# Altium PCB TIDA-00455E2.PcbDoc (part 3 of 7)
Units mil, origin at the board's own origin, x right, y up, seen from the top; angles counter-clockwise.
Board outline 6693 x 6693.1 mil, 8 copper layers (Layer 1 - Top Layer, Layer 2 - GND, Layer 3 - Sensitive, Layer 4 - GND, Layer 5 - PWR, Layer 6 - Signal, Layer 7 - GND, Layer 8 - Bottom Layer), stack 63.122 mil thick; 537 components, 407 nets, 1686 pads, 1249 vias.
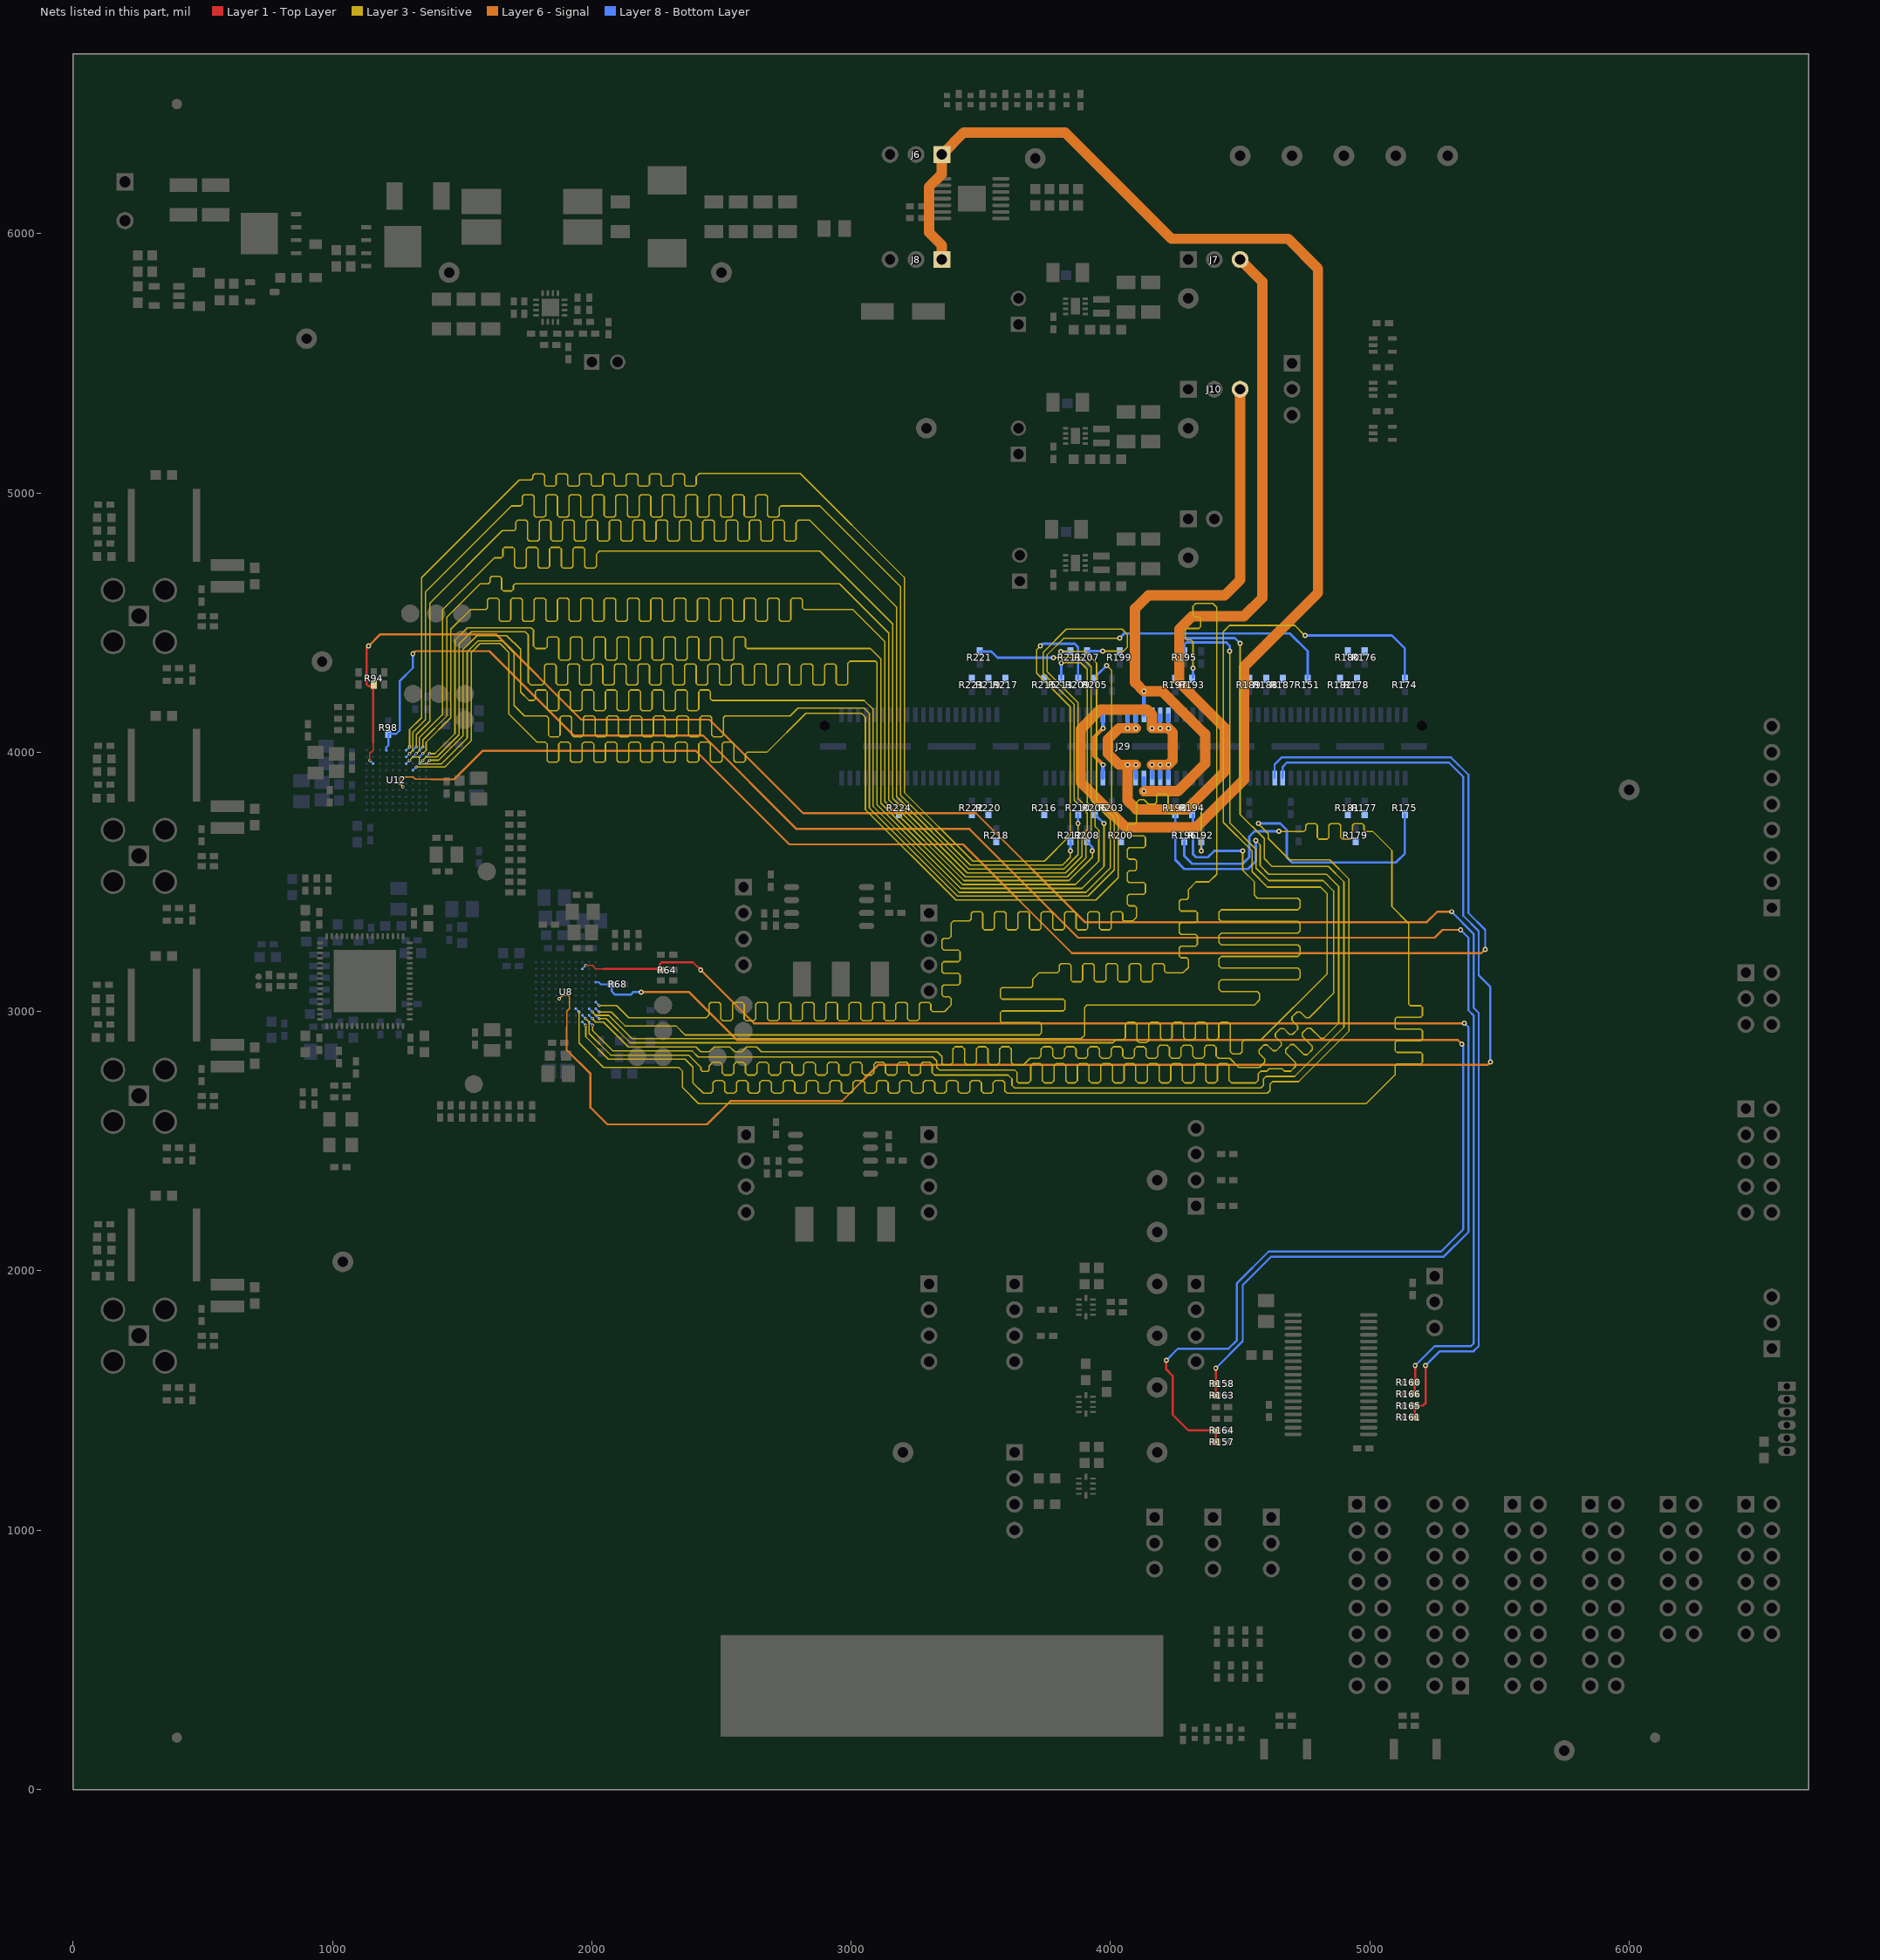
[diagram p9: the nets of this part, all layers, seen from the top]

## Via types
v1: diameter 20, hole 10, Layer 1 - Top Layer to Layer 8 - Bottom Layer, tented both sides, 1063 vias
v2: diameter 12, hole 6, Layer 1 - Top Layer to Layer 8 - Bottom Layer, tented bottom, 140 vias
v3: diameter 19.68, hole 7.87, Layer 1 - Top Layer to Layer 8 - Bottom Layer, 38 vias
v4: diameter 19.68, hole 7.87, Layer 1 - Top Layer to Layer 8 - Bottom Layer, tented top, 4 vias
v5: diameter 15.75, hole 7.87, Layer 1 - Top Layer to Layer 8 - Bottom Layer, 4 vias

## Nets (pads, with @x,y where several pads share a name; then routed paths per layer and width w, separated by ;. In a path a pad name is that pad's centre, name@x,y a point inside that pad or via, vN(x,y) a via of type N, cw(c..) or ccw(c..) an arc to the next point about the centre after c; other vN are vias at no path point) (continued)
DVP1_06: R192.2 U8.A4 | length 6138.7
  Layer 3 - Sensitive w5.5: v2(2027.95,3023.82) 2095,3023.82 2142.44,2976.38 2441.38,2976.38 2452.5,2987.5 2452.5,3028.25 2459.25,3035 2490.75,3035 2497.5,3028.25 2497.5,2971.75 2504.25,2965 2535.75,2965 2542.5,2971.75 2542.5,3028.25 2549.25,3035 2580.75,3035 2587.5,3028.25 2587.5,2971.75 2594.25,2965 2625.75,2965 2632.5,2971.75 2632.5,3028.25 2639.25,3035 2670.75,3035 2677.5,3028.25 2677.5,2971.75 2684.25,2965 2715.75,2965 2722.5,2971.75 2722.5,3028.25 2729.25,3035 2760.75,3035 2767.5,3028.25 2767.5,2971.75 2774.25,2965 2805.75,2965 2812.5,2971.75 2812.5,3028.25 2819.25,3035 2850.75,3035 2857.5,3028.25 2857.5,2971.75 2864.25,2965 2895.75,2965 2902.5,2971.75 2902.5,3028.25 2909.25,3035 2940.75,3035 2947.5,3028.25 2947.5,2971.75 2954.25,2965 2985.75,2965 2992.5,2971.75 2992.5,3028.25 2999.25,3035 3030.75,3035 3037.5,3028.25 3037.5,2971.75 3044.25,2965 3075.75,2965 3082.5,2971.75 3082.5,3028.25 3089.25,3035 3120.75,3035 3127.5,3028.25 3127.5,2971.75 3134.25,2965 3165.75,2965 3172.5,2971.75 3172.5,3028.25 3179.25,3035 3210.75,3035 3217.5,3028.25 3217.5,2971.75 3224.25,2965 3255.75,2965 3262.5,2971.75 3262.5,3028.25 3269.25,3035 3300.75,3035 3307.5,3028.25 3307.5,3006.75 3314.25,3000 3360,3000 3385,3025 3385,3050.75 3378.25,3057.5 3356.75,3057.5 3350,3064.25 3350,3095.75 3356.75,3102.5 3413.25,3102.5 3420,3109.25 3420,3140.75 3413.25,3147.5 3356.75,3147.5 3350,3154.25 3350,3185.75 3356.75,3192.5 3413.25,3192.5 3420,3199.25 3420,3230.75 3413.25,3237.5 3356.75,3237.5 3350,3244.25 3350,3275.75 3356.75,3282.5 3378.25,3282.5 3385,3289.25 3385,3340 3395,3350 3455.75,3350 3462.5,3356.75 3462.5,3378.25 3469.25,3385 3500.75,3385 3507.5,3378.25 3507.5,3321.75 3514.25,3315 3545.75,3315 3552.5,3321.75 3552.5,3378.25 3559.25,3385 3590.75,3385 3597.5,3378.25 3597.5,3321.75 3604.25,3315 3635.75,3315 3642.5,3321.75 3642.5,3378.25 3649.25,3385 3680.75,3385 3687.5,3378.25 3687.5,3321.75 3694.25,3315 3725.75,3315 3732.5,3321.75 3732.5,3378.25 3739.25,3385 3770.75,3385 3777.5,3378.25 3777.5,3321.75 3784.25,3315 3815.75,3315 3822.5,3321.75 3822.5,3378.25 3829.25,3385 3860.75,3385 3867.5,3378.25 3867.5,3321.75 3874.25,3315 3905.75,3315 3912.5,3321.75 3912.5,3378.25 3919.25,3385 3950.75,3385 3957.5,3378.25 3957.5,3321.75 3964.25,3315 3995.75,3315 4002.5,3321.75 4002.5,3378.25 4009.25,3385 4040.75,3385 4047.5,3378.25 4047.5,3352.5 4050,3350 4086,3350 4100,3364 4100,3400.75 4093.25,3407.5 4071.75,3407.5 4065,3414.25 4065,3445.75 4071.75,3452.5 4128.25,3452.5 4135,3459.25 4135,3490.75 4128.25,3497.5 4071.75,3497.5 4065,3504.25 4065,3535.75 4071.75,3542.5 4093.25,3542.5 4100,3549.25 4100,3580.75 4093.25,3587.5 4071.75,3587.5 4065,3594.25 4065,3625.75 4071.75,3632.5 4128.25,3632.5 4135,3639.25 4135,3670.75 4128.25,3677.5 4071.75,3677.5 4065,3684.25 4065,3715.75 4071.75,3722.5 4093.25,3722.5 4100,3729.25 4100,3806 4111,3817 4129,3817 4146,3800 4170.75,3800 4177.5,3806.75 4177.5,3831.88 4184.25,3838.63 4215.75,3838.63 4222.5,3831.88 4222.5,3768.12 4229.25,3761.37 4260.75,3761.37 4267.5,3768.12 4267.5,3793.25 4274.25,3800 4331,3800 4350,3781 v1(4350,3620)
  Layer 8 - Bottom Layer w5: U8.A4@2015.16,3036.61 v2(2027.95,3023.82)
  Layer 8 - Bottom Layer w9.5: v1(4350,3620) R192.2@4350,3656.38
DVP1_07: R193.1 U8.A3 | length 6132
  Layer 3 - Sensitive w5.5: v2(2027.95,2998.23) 2075,2998.23 2128.35,2944.88 2325,2944.88 2359.88,2910 3726,2910 3734,2918 3734,2949 3725.5,2957.5 3581.75,2957.5 3575,2964.25 3575,2995.75 3581.75,3002.5 3818.25,3002.5 3825,3009.25 3825,3040.75 3818.25,3047.5 3581.75,3047.5 3575,3054.25 3575,3085.75 3581.75,3092.5 3693.25,3092.5 3700,3099.25 3700,3125 3725,3150 3795.75,3150 3802.5,3156.75 3802.5,3178.25 3809.25,3185 3840.75,3185 3847.5,3178.25 3847.5,3121.75 3854.25,3115 3885.75,3115 3892.5,3121.75 3892.5,3178.25 3899.25,3185 3930.75,3185 3937.5,3178.25 3937.5,3121.75 3944.25,3115 3975.75,3115 3982.5,3121.75 3982.5,3178.25 3989.25,3185 4020.75,3185 4027.5,3178.25 4027.5,3121.75 4034.25,3115 4065.75,3115 4072.5,3121.75 4072.5,3178.25 4079.25,3185 4110.75,3185 4117.5,3178.25 4117.5,3121.75 4124.25,3115 4155.75,3115 4162.5,3121.75 4162.5,3178.25 4169.25,3185 4200.75,3185 4207.5,3178.25 4207.5,3156.75 4214.25,3150 4280,3150 4300,3170 4300,3200.75 4293.25,3207.5 4271.75,3207.5 4265,3214.25 4265,3245.75 4271.75,3252.5 4328.25,3252.5 4335,3259.25 4335,3290.75 4328.25,3297.5 4271.75,3297.5 4265,3304.25 4265,3335.75 4271.75,3342.5 4328.25,3342.5 4335,3349.25 4335,3380.75 4328.25,3387.5 4271.75,3387.5 4265,3394.25 4265,3425.75 4271.75,3432.5 4293.25,3432.5 4300,3439.25 4300,3470 4330,3500 4380,3500 4410,3530 4410,4559.27 4395,4574.27 4329.27,4574.27 4318,4563 4318,4529.25 4324.75,4522.5 4341.07,4522.5 4347.82,4515.75 4347.82,4484.25 4341.07,4477.5 4294.93,4477.5 4288.18,4470.75 4288.18,4439.25 4294.93,4432.5 4311.25,4432.5 4318,4425.75 v1(4318,4324.38)
  Layer 8 - Bottom Layer w5: U8.A3@2015.16,3011.02 v2(2027.95,2998.23)
  Layer 8 - Bottom Layer w9.5: R193.1@4318,4288 v1(4318,4324.38)
DVP1_08: R194.2 U8.B3 | length 6139.7
  Layer 3 - Sensitive w5.5: v2(2002.36,2998.23) 2015.19,2985.4 2064.74,2985.4 2155.02,2895.12 3887.12,2895.12 3900,2908 3900,3016 3909,3025 4555,3025 4575,3045 4575,3068.5 4566,3077.5 4427.55,3077.5 4418.55,3086.5 4418.55,3113.5 4427.55,3122.5 4722.45,3122.5 4731.45,3131.5 4731.45,3158.5 4722.45,3167.5 4427.55,3167.5 4418.55,3176.5 4418.55,3203.5 4427.55,3212.5 4722.45,3212.5 4731.45,3221.5 4731.45,3248.5 4722.45,3257.5 4427.55,3257.5 4418.55,3266.5 4418.55,3293.5 4427.55,3302.5 4722.45,3302.5 4731.45,3311.5 4731.45,3338.5 4722.45,3347.5 4427.55,3347.5 4418.55,3356.5 4418.55,3383.5 4427.55,3392.5 4722.45,3392.5 4731.45,3401.5 4731.45,3428.5 4722.45,3437.5 4566.5,3437.5 4555,3449 4555,3500 4510,3545 v1(4510,3620)
  Layer 8 - Bottom Layer w5: U8.B3@1989.57,3011.02 v2(2002.36,2998.23)
  Layer 8 - Bottom Layer w9.5: R194.2@4318,3760 4318,3607 4330,3595 4375,3595 4400,3620 v1(4510,3620)
DVP1_09: R195.1 U8.B2 | length 6137.7
  Layer 3 - Sensitive w5.5: v2(2002.36,2972.64) 2015.19,2959.81 2045.19,2959.81 2141.38,2863.62 2401.38,2863.62 2420,2845 2453,2845 2472,2864 2532,2864 2551,2845 2578,2845 2597,2864 2635,2864 2654,2845 3332,2845 3350,2827 3350,2800 3355,2795 3383.5,2795 3392.5,2804 3392.5,2855.37 3401.5,2864.37 3428.5,2864.37 3437.5,2855.37 3437.5,2804 3446.5,2795 3473.5,2795 3482.5,2804 3482.5,2855.37 3491.5,2864.37 3518.5,2864.37 3527.5,2855.37 3527.5,2804 3536.5,2795 3563.5,2795 3572.5,2804 3572.5,2855.37 3581.5,2864.37 3608.5,2864.37 3617.5,2855.37 3617.5,2804 3626.5,2795 3665,2795 3690,2820 3723.5,2820 3732.5,2829 3732.5,2855.37 3741.5,2864.37 3768.5,2864.37 3777.5,2855.37 3777.5,2829 3786.5,2820 3813.5,2820 3822.5,2829 3822.5,2855.37 3831.5,2864.37 3858.5,2864.37 3867.5,2855.37 3867.5,2829 3876.5,2820 3903.5,2820 3912.5,2829 3912.5,2855.37 3921.5,2864.37 3948.5,2864.37 3957.5,2855.37 3957.5,2829 3966.5,2820 3993.5,2820 4002.5,2829 4002.5,2855.37 4011.5,2864.37 4038.5,2864.37 4047.5,2855.37 4047.5,2829 4056.5,2820 4083.5,2820 4092.5,2829 4092.5,2855.37 4101.5,2864.37 4128.5,2864.37 4137.5,2855.37 4137.5,2829 4146.5,2820 4173.5,2820 4182.5,2829 4182.5,2861 4191.5,2870 4218.5,2870 4227.5,2861 4227.5,2829 4236.5,2820 4263.5,2820 4272.5,2829 4272.5,2861 4281.5,2870 4308.5,2870 4317.5,2861 4317.5,2829 4326.5,2820 4353.5,2820 4362.5,2829 4362.5,2861 4371.5,2870 4398.5,2870 4407.5,2861 4407.5,2829 4416.5,2820 4460,2820 4495,2785 4575,2785 4594.55,2804.55 4594.55,2817.27 4572.55,2839.27 4572.55,2852 4591.64,2871.09 4604.37,2871.09 4626.37,2849.09 4639.09,2849.09 4658.19,2868.19 4658.19,2880.91 4636.19,2902.91 4636.19,2915.64 4655.28,2934.73 4668.01,2934.73 4690.01,2912.73 4702.73,2912.73 4721.83,2931.83 4721.83,2944.55 4699.83,2966.55 4699.83,2979.28 4718.92,2998.37 4731.65,2998.37 4753.65,2976.37 4766.37,2976.37 4860,3070 4860,3465 4820,3505 4610,3505 4561.38,3553.62 4561.38,3625.89 4460,3727.27 v1(4460,4390)
  Layer 8 - Bottom Layer w5: U8.B2@1989.57,2985.43 v2(2002.36,2972.64)
  Layer 8 - Bottom Layer w9.5: R195.1@4285,4388.62 4285,4415 4293,4423 4447,4423 4460,4410 v1(4460,4390)
DVP1_10: R196.2 U8.D3 | length 6139.7
  Layer 3 - Sensitive w5.5: v2(1951.18,2998.23) 1951.18,2878.82 2045.12,2784.88 2335,2784.88 2350,2769.88 2350,2707 2412,2645 4986,2645 5097.13,2756.13 5097.13,2790.75 5103.88,2797.5 5196.12,2797.5 5202.87,2804.25 5202.87,2835.75 5196.12,2842.5 5103.88,2842.5 5097.13,2849.25 5097.13,2880.75 5103.88,2887.5 5196.12,2887.5 5202.87,2894.25 5202.87,2925.75 5196.12,2932.5 5103.88,2932.5 5097.13,2939.25 5097.13,2970.75 5103.88,2977.5 5196.12,2977.5 5202.87,2984.25 5202.87,3015.75 5196.12,3022.5 5156.75,3022.5 5150,3029.25 5150,3340 5085,3405 5085,3621 5011,3695 4984.25,3695 4977.5,3701.75 4977.5,3718.25 4970.75,3725 4939.25,3725 4932.5,3718.25 4932.5,3671.75 4925.75,3665 4894.25,3665 4887.5,3671.75 4887.5,3718.25 4880.75,3725 4849.25,3725 4842.5,3718.25 4842.5,3671.75 4835.75,3665 4804.25,3665 4797.5,3671.75 4797.5,3718.25 4790.75,3725 4759.25,3725 4752.5,3718.25 4752.5,3701.75 4745.75,3695 v1(4650,3695)
  Layer 8 - Bottom Layer w5: U8.D3@1938.39,3011.02 v2(1951.18,2998.23)
  Layer 8 - Bottom Layer w9.5: R196.2@4285,3656.38 4285,3600 4315,3570 4510,3570 4535,3595 4535,3675 4555,3695 v1(4650,3695)
DVP1_11: R197.1 U8.C2 | length 6138.4
  Layer 3 - Sensitive w5.5: v2(1976.77,2972.64) 1989.6,2959.81 1989.6,2915.4 2072.87,2832.13 2372.87,2832.13 2421,2784 2421,2775 2427,2769 2447,2769 2452.08,2774.08 2452.08,2789.92 2466.5,2804.35 2493.5,2804.35 2502.5,2795.35 2502.5,2764 2511.5,2755 2538.5,2755 2547.5,2764 2547.5,2795.35 2556.5,2804.35 2583.5,2804.35 2592.5,2795.35 2592.5,2764 2601.5,2755 2628.5,2755 2637.5,2764 2637.5,2795.35 2646.5,2804.35 2673.5,2804.35 2682.5,2795.35 2682.5,2764 2691.5,2755 2718.5,2755 2727.5,2764 2727.5,2795.35 2736.5,2804.35 2763.5,2804.35 2772.5,2795.35 2772.5,2764 2781.5,2755 2808.5,2755 2817.5,2764 2817.5,2795.35 2826.5,2804.35 2853.5,2804.35 2862.5,2795.35 2862.5,2764 2871.5,2755 2898.5,2755 2907.5,2764 2907.5,2795.35 2916.5,2804.35 2943.5,2804.35 2952.5,2795.35 2952.5,2764 2961.5,2755 2988.5,2755 2997.5,2764 2997.5,2795.35 3006.5,2804.35 3033.5,2804.35 3042.5,2795.35 3042.5,2764 3051.5,2755 3078.5,2755 3087.5,2764 3087.5,2795.35 3096.5,2804.35 3123.5,2804.35 3132.5,2795.35 3132.5,2764 3141.5,2755 3168.5,2755 3177.5,2764 3177.5,2795.35 3186.5,2804.35 3213.5,2804.35 3222.5,2795.35 3222.5,2764 3231.5,2755 3258.5,2755 3267.5,2764 3267.5,2795.35 3276.5,2804.35 3303.5,2804.35 3312.5,2795.35 3312.5,2764 3321.5,2755 3605,2755 3620,2740 3620,2715 3630,2705 4580,2705 4590,2715 4590,2740 4600,2750 4710,2750 4900,2940 4900,3500 4840,3560 4622.87,3560 4592.87,3590 4592.87,3667.13 4500,3760 v1(4500,4420)
  Layer 8 - Bottom Layer w5: U8.C2@1963.98,2985.43 v2(1976.77,2972.64)
  Layer 8 - Bottom Layer w9.5: R197.1@4250,4283.62 4250,4415 4275,4440 4480,4440 v1(4500,4420)
DVP1_HSYNC: R174.1 U8.A2 | length 6139.1
  Layer 3 - Sensitive w5.5: v2(2027.95,2972.64) 2055,2972.64 2148.27,2879.37 4009.37,2879.37 4020,2890 4048.5,2890 4057.5,2899 4057.5,2949.48 4066.5,2958.48 4093.5,2958.48 4102.5,2949.48 4102.5,2889 4111.5,2880 4138.5,2880 4147.5,2889 4147.5,2949.48 4156.5,2958.48 4183.5,2958.48 4192.5,2949.48 4192.5,2899 4201.5,2890 4228.5,2890 4237.5,2899 4237.5,2949.48 4246.5,2958.48 4273.5,2958.48 4282.5,2949.48 4282.5,2899 4291.5,2890 4318.5,2890 4327.5,2899 4327.5,2949.48 4336.5,2958.48 4363.5,2958.48 4372.5,2949.48 4372.5,2899 4381.5,2890 4408.5,2890 4417.5,2899 4417.5,2949.48 4426.5,2958.48 4453.5,2958.48 4462.5,2949.48 4462.5,2845.23 4471.5,2836.23 4498.5,2836.23 4507.5,2845.23 4507.5,2881 4516.5,2890 4580,2890 4835,3145 4835,3455 4810,3480 4605,3480 4545.63,3539.37 4545.63,3619.37 4435,3730 4435,4465 4459,4489 4711,4489 v1(4750,4450)
  Layer 8 - Bottom Layer w5: U8.A2@2015.16,2985.43 v2(2027.95,2972.64)
  Layer 8 - Bottom Layer w9.5: v1(4750,4450) 5085,4450 5135,4400 R174.1@5135,4283.62
DVP1_PCLK: R198.2 U8.B1 | length 6121.6
  Layer 3 - Sensitive w5.5: v2(2002.36,2947.05) 2002.36,2927.64 2082.13,2847.87 2387.13,2847.87 2410,2825 3315,2825 3330,2810 3330,2785 3340,2775 3630,2775 3640,2765 3640,2730 3645,2725 3683.5,2725 3692.5,2734 3692.5,2791 3701.5,2800 3728.5,2800 3737.5,2791 3737.5,2734 3746.5,2725 3773.5,2725 3782.5,2734 3782.5,2791 3791.5,2800 3818.5,2800 3827.5,2791 3827.5,2734 3836.5,2725 3863.5,2725 3872.5,2734 3872.5,2791 3881.5,2800 3908.5,2800 3917.5,2791 3917.5,2734 3926.5,2725 3953.5,2725 3962.5,2734 3962.5,2791 3971.5,2800 3998.5,2800 4007.5,2791 4007.5,2734 4016.5,2725 4043.5,2725 4052.5,2734 4052.5,2791 4061.5,2800 4088.5,2800 4097.5,2791 4097.5,2734 4106.5,2725 4133.5,2725 4142.5,2734 4142.5,2791 4151.5,2800 4178.5,2800 4187.5,2791 4187.5,2734 4196.5,2725 4223.5,2725 4232.5,2734 4232.5,2791 4241.5,2800 4268.5,2800 4277.5,2791 4277.5,2734 4286.5,2725 4313.5,2725 4322.5,2734 4322.5,2791 4331.5,2800 4358.5,2800 4367.5,2791 4367.5,2734 4376.5,2725 4403.5,2725 4412.5,2734 4412.5,2791 4421.5,2800 4448.5,2800 4457.5,2791 4457.5,2734 4466.5,2725 4560,2725 4570,2735 4570,2760 4580,2770 4603,2770 4612,2779 4661,2779 4670,2770 4695,2770 4714.55,2789.55 4714.55,2802.27 4675.93,2840.89 4675.93,2853.62 4695.02,2872.71 4707.75,2872.71 4746.37,2834.09 4759.09,2834.09 4778.19,2853.19 4778.19,2865.91 4739.56,2904.53 4739.56,2917.26 4758.66,2936.35 4771.38,2936.35 4810.01,2897.73 4822.73,2897.73 4880,2955 4880,3483 4833,3530 4610,3530 4577.13,3562.87 4577.13,3642.87 v1(4560,3660)
  Layer 8 - Bottom Layer w5: U8.B1@1989.57,2959.84 v2(2002.36,2947.05)
  Layer 8 - Bottom Layer w9.5: R198.2@4250,3761.38 4250,3585 4285,3550 4530,3550 4560,3580 v1(4560,3660)
DVP1_VSYNC: R175.2 U8.C1 | length 6139.2
  Layer 3 - Sensitive w5.5: v2(1976.77,2947.05) 1976.77,2903.23 2063.62,2816.38 2360,2816.38 2390,2786.38 2390,2725 2430,2685 2458.5,2685 2467.5,2694 2467.5,2725.16 2476.5,2734.16 2503.5,2734.16 2512.5,2725.16 2512.5,2694 2521.5,2685 2548.5,2685 2557.5,2694 2557.5,2725.16 2566.5,2734.16 2593.5,2734.16 2602.5,2725.16 2602.5,2694 2611.5,2685 2638.5,2685 2647.5,2694 2647.5,2725.16 2656.5,2734.16 2683.5,2734.16 2692.5,2725.16 2692.5,2694 2701.5,2685 2728.5,2685 2737.5,2694 2737.5,2725.16 2746.5,2734.16 2773.5,2734.16 2782.5,2725.16 2782.5,2694 2791.5,2685 2818.5,2685 2827.5,2694 2827.5,2725.16 2836.5,2734.16 2863.5,2734.16 2872.5,2725.16 2872.5,2694 2881.5,2685 2908.5,2685 2917.5,2694 2917.5,2725.16 2926.5,2734.16 2953.5,2734.16 2962.5,2725.16 2962.5,2694 2971.5,2685 2998.5,2685 3007.5,2694 3007.5,2725.16 3016.5,2734.16 3043.5,2734.16 3052.5,2725.16 3052.5,2694 3061.5,2685 3088.5,2685 3097.5,2694 3097.5,2725.16 3106.5,2734.16 3133.5,2734.16 3142.5,2725.16 3142.5,2694 3151.5,2685 3178.5,2685 3187.5,2694 3187.5,2725.16 3196.5,2734.16 3223.5,2734.16 3232.5,2725.16 3232.5,2694 3241.5,2685 3268.5,2685 3277.5,2694 3277.5,2725.16 3286.5,2734.16 3313.5,2734.16 3322.5,2725.16 3322.5,2694 3331.5,2685 3358.5,2685 3367.5,2694 3367.5,2725.16 3376.5,2734.16 3403.5,2734.16 3412.5,2725.16 3412.5,2694 3421.5,2685 3448.5,2685 3457.5,2694 3457.5,2725.16 3466.5,2734.16 3493.5,2734.16 3502.5,2725.16 3502.5,2694 3511.5,2685 3538.5,2685 3547.5,2694 3547.5,2725.16 3556.5,2734.16 3583.5,2734.16 3592.5,2725.16 3592.5,2694 3601.5,2685 4605,2685 4615,2695 4615,2720 4625,2730 4725,2730 4920,2925 4920,3510 4845,3585 4691,3585 4608.62,3667.38 4608.62,3686.38 v1(4570,3725)
  Layer 8 - Bottom Layer w5: U8.C1@1963.98,2959.84 v2(1976.77,2947.05)
  Layer 8 - Bottom Layer w9.5: v1(4570,3725) 4655,3725 4680,3700 4680,3595 4700,3575 5100,3575 5135,3610 R175.2@5135,3761.38
DVP2_04: R211.1 U12.C4 | length 6132
  Layer 3 - Sensitive w5.5: v2(1297.42,3969.27) 1310.15,3982 ; 1310.15,3982.1 1330.65,3982.1 1335.85,3976.9 1335.85,3962.64 1343.49,3955 1420,3955 1519.37,4054.37 1519.37,4387.37 1562,4430 1654,4430 1700,4384 1700,4181 1741,4140 1825.75,4140 1832.5,4133.25 1832.5,4066.75 1839.25,4060 1870.75,4060 1877.5,4066.75 1877.5,4133.25 1884.25,4140 1915.75,4140 1922.5,4133.25 1922.5,4066.75 1929.25,4060 1960.75,4060 1967.5,4066.75 1967.5,4133.25 1974.25,4140 2005.75,4140 2012.5,4133.25 2012.5,4066.75 2019.25,4060 2050.75,4060 2057.5,4066.75 2057.5,4133.25 2064.25,4140 2095.75,4140 2102.5,4133.25 2102.5,4066.75 2109.25,4060 2140.75,4060 2147.5,4066.75 2147.5,4133.25 2154.25,4140 2185.75,4140 2192.5,4133.25 2192.5,4066.75 2199.25,4060 2230.75,4060 2237.5,4066.75 2237.5,4133.25 2244.25,4140 2275.75,4140 2282.5,4133.25 2282.5,4066.75 2289.25,4060 2320.75,4060 2327.5,4066.75 2327.5,4133.25 2334.25,4140 2365.75,4140 2372.5,4133.25 2372.5,4066.75 2379.25,4060 2410.75,4060 2417.5,4066.75 2417.5,4133.25 2424.25,4140 2455.75,4140 2462.5,4133.25 2462.5,4066.75 2469.25,4060 2500.75,4060 2507.5,4066.75 2507.5,4133.25 2514.25,4140 2765,4140 2795,4170 3050,4170 3070,4150 3070,3785.15 3410.15,3445 3914,3445 4015,3546 4015,3746.21 3946.21,3815 3946.21,4343.79 3901.38,4388.62 v1(3808.62,4388.62)
  Layer 8 - Bottom Layer w5: U12.C4@1284.63,3956.48 v2(1297.42,3969.27)
  Layer 8 - Bottom Layer w9.5: v1(3808.62,4388.62) R211.1@3845,4388.62
DVP2_05: R212.2 U12.B4 | length 6133.9
  Layer 3 - Sensitive w5.5: v2(1297.42,3994.86) 1310.25,4007.69 1310.25,4077.25 1359.37,4126.37 1359.37,4619.37 1690,4950 1725.75,4950 1732.5,4956.75 1732.5,4986.58 1739.25,4993.33 1770.75,4993.33 1777.5,4986.58 1777.5,4913.42 1784.25,4906.67 1815.75,4906.67 1822.5,4913.42 1822.5,4986.58 1829.25,4993.33 1860.75,4993.33 1867.5,4986.58 1867.5,4913.42 1874.25,4906.67 1905.75,4906.67 1912.5,4913.42 1912.5,4986.58 1919.25,4993.33 1950.75,4993.33 1957.5,4986.58 1957.5,4913.42 1964.25,4906.67 1995.75,4906.67 2002.5,4913.42 2002.5,4986.58 2009.25,4993.33 2040.75,4993.33 2047.5,4986.58 2047.5,4913.42 2054.25,4906.67 2085.75,4906.67 2092.5,4913.42 2092.5,4986.58 2099.25,4993.33 2130.75,4993.33 2137.5,4986.58 2137.5,4913.42 2144.25,4906.67 2175.75,4906.67 2182.5,4913.42 2182.5,4986.58 2189.25,4993.33 2220.75,4993.33 2227.5,4986.58 2227.5,4913.42 2234.25,4906.67 2265.75,4906.67 2272.5,4913.42 2272.5,4986.58 2279.25,4993.33 2310.75,4993.33 2317.5,4986.58 2317.5,4913.42 2324.25,4906.67 2355.75,4906.67 2362.5,4913.42 2362.5,4986.58 2369.25,4993.33 2400.75,4993.33 2407.5,4986.58 2407.5,4913.42 2414.25,4906.67 2445.75,4906.67 2452.5,4913.42 2452.5,4986.58 2459.25,4993.33 2490.75,4993.33 2497.5,4986.58 2497.5,4913.42 2504.25,4906.67 2535.75,4906.67 2542.5,4913.42 2542.5,4986.58 2549.25,4993.33 2580.75,4993.33 2587.5,4986.58 2587.5,4913.42 2594.25,4906.67 2625.75,4906.67 2632.5,4913.42 2632.5,4986.58 2639.25,4993.33 2670.75,4993.33 2677.5,4986.58 2677.5,4913.42 2684.25,4906.67 2715.75,4906.67 2722.5,4913.42 2722.5,4943.25 2729.25,4950 2879,4950 3190,4639 3190,3835 3460,3565 3815,3565 3845,3595 v1(3845,3620)
  Layer 8 - Bottom Layer w5: U12.B4@1284.63,3982.07 v2(1297.42,3994.86)
  Layer 8 - Bottom Layer w9.5: v1(3845,3620) R212.2@3845,3656.38
DVP2_06: R209.1 U12.A4 | length 6136.2
  Layer 3 - Sensitive w5.5: v2(1297.42,4020.45) 1297.42,4087.5 1343.62,4133.7 1343.62,4673.62 1720,5050 1765.75,5050 1772.5,5056.75 1772.5,5067.33 1779.25,5074.08 1810.75,5074.08 1817.5,5067.33 1817.5,5032.67 1824.25,5025.92 1855.75,5025.92 1862.5,5032.67 1862.5,5067.33 1869.25,5074.08 1900.75,5074.08 1907.5,5067.33 1907.5,5032.67 1914.25,5025.92 1945.75,5025.92 1952.5,5032.67 1952.5,5067.33 1959.25,5074.08 1990.75,5074.08 1997.5,5067.33 1997.5,5032.67 2004.25,5025.92 2035.75,5025.92 2042.5,5032.67 2042.5,5067.33 2049.25,5074.08 2080.75,5074.08 2087.5,5067.33 2087.5,5032.67 2094.25,5025.92 2125.75,5025.92 2132.5,5032.67 2132.5,5067.33 2139.25,5074.08 2170.75,5074.08 2177.5,5067.33 2177.5,5032.67 2184.25,5025.92 2215.75,5025.92 2222.5,5032.67 2222.5,5067.33 2229.25,5074.08 2260.75,5074.08 2267.5,5067.33 2267.5,5032.67 2274.25,5025.92 2305.75,5025.92 2312.5,5032.67 2312.5,5067.33 2319.25,5074.08 2350.75,5074.08 2357.5,5067.33 2357.5,5032.67 2364.25,5025.92 2395.75,5025.92 2402.5,5032.67 2402.5,5062.5 2415,5075 2804,5075 3205,4674 3205,3845 3470,3580 3745,3580 3845,3680 3845,4175 3715,4305 3715,4395 v1(3730,4410)
  Layer 8 - Bottom Layer w5: U12.A4@1284.63,4007.66 v2(1297.42,4020.45)
  Layer 8 - Bottom Layer w9.5: v1(3730,4410) 3738,4418 3862,4418 3875,4405 R209.1@3875,4283.62
DVP2_07: R210.2 U12.A3 | length 6133.4
  Layer 3 - Sensitive w5.5: v2(1323.01,4020.45) 1323.01,4067.5 1375.12,4119.61 1375.12,4575.12 1655,4855 1700.75,4855 1707.5,4861.75 1707.5,4888.21 1714.25,4894.96 1745.75,4894.96 1752.5,4888.21 1752.5,4821.79 1759.25,4815.04 1790.75,4815.04 1797.5,4821.79 1797.5,4888.21 1804.25,4894.96 1835.75,4894.96 1842.5,4888.21 1842.5,4821.79 1849.25,4815.04 1880.75,4815.04 1887.5,4821.79 1887.5,4888.21 1894.25,4894.96 1925.75,4894.96 1932.5,4888.21 1932.5,4821.79 1939.25,4815.04 1970.75,4815.04 1977.5,4821.79 1977.5,4888.21 1984.25,4894.96 2015.75,4894.96 2022.5,4888.21 2022.5,4821.79 2029.25,4815.04 2060.75,4815.04 2067.5,4821.79 2067.5,4888.21 2074.25,4894.96 2105.75,4894.96 2112.5,4888.21 2112.5,4821.79 2119.25,4815.04 2150.75,4815.04 2157.5,4821.79 2157.5,4888.21 2164.25,4894.96 2195.75,4894.96 2202.5,4888.21 2202.5,4821.79 2209.25,4815.04 2240.75,4815.04 2247.5,4821.79 2247.5,4888.21 2254.25,4894.96 2285.75,4894.96 2292.5,4888.21 2292.5,4821.79 2299.25,4815.04 2330.75,4815.04 2337.5,4821.79 2337.5,4888.21 2344.25,4894.96 2375.75,4894.96 2382.5,4888.21 2382.5,4821.79 2389.25,4815.04 2420.75,4815.04 2427.5,4821.79 2427.5,4888.21 2434.25,4894.96 2465.75,4894.96 2472.5,4888.21 2472.5,4821.79 2479.25,4815.04 2510.75,4815.04 2517.5,4821.79 2517.5,4888.21 2524.25,4894.96 2555.75,4894.96 2562.5,4888.21 2562.5,4821.79 2569.25,4815.04 2600.75,4815.04 2607.5,4821.79 2607.5,4888.21 2614.25,4894.96 2645.75,4894.96 2652.5,4888.21 2652.5,4821.79 2659.25,4815.04 2690.75,4815.04 2697.5,4821.79 2697.5,4888.21 2704.25,4894.96 2735.75,4894.96 2742.5,4888.21 2742.5,4821.79 2749.25,4815.04 2780.75,4815.04 2787.5,4821.79 2787.5,4885.5 2797,4895 2840,4895 3175,4560 3175,3828.79 3453.79,3550 3820,3550 3875,3605 v1(3875,3725)
  Layer 8 - Bottom Layer w5: U12.A3@1310.22,4007.66 v2(1323.01,4020.45)
  Layer 8 - Bottom Layer w9.5: v1(3875,3725) R210.2@3875,3761.38
DVP2_08: R207.1 U12.B3 | length 6136.3
  Layer 3 - Sensitive w5.5: v2(1323.01,3994.86) 1335.84,4007.69 1335.84,4057.4 ; 1336,4057.4 1424.88,4146.28 1424.88,4549.88 1625,4750 1650.75,4750 1657.5,4756.75 1657.5,4783.25 1664.25,4790 1695.75,4790 1702.5,4783.25 1702.5,4716.75 1709.25,4710 1740.75,4710 1747.5,4716.75 1747.5,4783.25 1754.25,4790 1785.75,4790 1792.5,4783.25 1792.5,4716.75 1799.25,4710 1830.75,4710 1837.5,4716.75 1837.5,4783.25 1844.25,4790 1875.75,4790 1882.5,4783.25 1882.5,4716.75 1889.25,4710 1920.75,4710 1927.5,4716.75 1927.5,4783.25 1934.25,4790 1965.75,4790 1972.5,4783.25 1972.5,4716.75 1979.25,4710 2010.75,4710 2017.5,4716.75 2017.5,4763.5 2030,4776 2879,4776 3160,4495 3160,3822.57 3447.57,3535 3826.21,3535 3890,3598.79 3890,3681.21 3910,3701.21 3910,3765 3860,3815 3860,4185 3740,4305 3740,4385 3830,4475 4045,4475 4065,4455 4065,4405 4050,4390 v1(3970,4390)
  Layer 8 - Bottom Layer w5: U12.B3@1310.22,3982.07 v2(1323.01,3994.86) ; R207.1@3910,4388.62 R207.1@3911.38,4390
  Layer 8 - Bottom Layer w9.5: R207.1@3911.38,4390 v1(3970,4390)
DVP2_09: R208.2 U12.B2 | length 6135.9
  Layer 3 - Sensitive w5.5: v2(1348.6,3994.86) 1361.43,4007.69 1361.43,4038.5 ; 1361.5,4038.5 1456.38,4133.38 1456.38,4474.38 1532,4550 1590.75,4550 1597.5,4556.75 1597.5,4587.86 1604.25,4594.61 1635.75,4594.61 1642.5,4587.86 1642.5,4512.14 1649.25,4505.39 1680.75,4505.39 1687.5,4512.14 1687.5,4587.86 1694.25,4594.61 1725.75,4594.61 1732.5,4587.86 1732.5,4512.14 1739.25,4505.39 1770.75,4505.39 1777.5,4512.14 1777.5,4587.86 1784.25,4594.61 1815.75,4594.61 1822.5,4587.86 1822.5,4512.14 1829.25,4505.39 1860.75,4505.39 1867.5,4512.14 1867.5,4587.86 1874.25,4594.61 1905.75,4594.61 1912.5,4587.86 1912.5,4512.14 1919.25,4505.39 1950.75,4505.39 1957.5,4512.14 1957.5,4587.86 1964.25,4594.61 1995.75,4594.61 2002.5,4587.86 2002.5,4512.14 2009.25,4505.39 2040.75,4505.39 2047.5,4512.14 2047.5,4587.86 2054.25,4594.61 2085.75,4594.61 2092.5,4587.86 2092.5,4512.14 2099.25,4505.39 2130.75,4505.39 2137.5,4512.14 2137.5,4587.86 2144.25,4594.61 2175.75,4594.61 2182.5,4587.86 2182.5,4512.14 2189.25,4505.39 2220.75,4505.39 2227.5,4512.14 2227.5,4587.86 2234.25,4594.61 2265.75,4594.61 2272.5,4587.86 2272.5,4512.14 2279.25,4505.39 2310.75,4505.39 2317.5,4512.14 2317.5,4587.86 2324.25,4594.61 2355.75,4594.61 2362.5,4587.86 2362.5,4512.14 2369.25,4505.39 2400.75,4505.39 2407.5,4512.14 2407.5,4587.86 2414.25,4594.61 2445.75,4594.61 2452.5,4587.86 2452.5,4512.14 2459.25,4505.39 2490.75,4505.39 2497.5,4512.14 2497.5,4587.86 2504.25,4594.61 2535.75,4594.61 2542.5,4587.86 2542.5,4512.14 2549.25,4505.39 2580.75,4505.39 2587.5,4512.14 2587.5,4587.86 2594.25,4594.61 2625.75,4594.61 2632.5,4587.86 2632.5,4512.14 2639.25,4505.39 2670.75,4505.39 2677.5,4512.14 2677.5,4587.86 2684.25,4594.61 2715.75,4594.61 2722.5,4587.86 2722.5,4512.14 2729.25,4505.39 2760.75,4505.39 2767.5,4512.14 2767.5,4587.86 2774.25,4594.61 2805.75,4594.61 2812.5,4587.86 2812.5,4556.75 2819.25,4550 3007,4550 3130,4427 3130,3810 3435,3505 3840,3505 3930,3595 v1(3930,3620)
  Layer 8 - Bottom Layer w5: U12.B2@1335.81,3982.07 v2(1348.6,3994.86) ; R208.2@3910,3655 R208.2@3910,3656.38
  Layer 8 - Bottom Layer w9.5: R208.2@3910,3655 3930,3635 v1(3930,3620)
DVP2_10: R205.1 U12.D3 | length 6135.5
  Layer 3 - Sensitive w5.5: v2(1323.01,3943.68) 1433.68,3943.68 1535.12,4045.12 1535.12,4385.12 1569,4419 1646,4419 1680,4385 1680,4147.86 1789.25,4038.61 1820.75,4038.61 1827.5,4031.86 1827.5,3968.14 1834.25,3961.39 1865.75,3961.39 1872.5,3968.14 1872.5,4031.86 1879.25,4038.61 1910.75,4038.61 1917.5,4031.86 1917.5,3968.14 1924.25,3961.39 1955.75,3961.39 1962.5,3968.14 1962.5,4031.86 1969.25,4038.61 2000.75,4038.61 2007.5,4031.86 2007.5,3968.14 2014.25,3961.39 2045.75,3961.39 2052.5,3968.14 2052.5,4031.86 2059.25,4038.61 2090.75,4038.61 2097.5,4031.86 2097.5,3968.14 2104.25,3961.39 2135.75,3961.39 2142.5,3968.14 2142.5,4031.86 2149.25,4038.61 2180.75,4038.61 2187.5,4031.86 2187.5,3968.14 2194.25,3961.39 2225.75,3961.39 2232.5,3968.14 2232.5,4031.86 2239.25,4038.61 2270.75,4038.61 2277.5,4031.86 2277.5,3968.14 2284.25,3961.39 2315.75,3961.39 2322.5,3968.14 2322.5,4031.86 2329.25,4038.61 2360.75,4038.61 2367.5,4031.86 2367.5,3968.14 2374.25,3961.39 2405.75,3961.39 2412.5,3968.14 2412.5,4031.86 2419.25,4038.61 2450.75,4038.61 2457.5,4031.86 2457.5,3968.14 2464.25,3961.39 2495.75,3961.39 2502.5,3968.14 2502.5,4031.86 2509.25,4038.61 2540.75,4038.61 2547.5,4031.86 2547.5,3968.14 2554.25,3961.39 2585.75,3961.39 2592.5,3968.14 2592.5,3993.25 2599.25,4000 2675,4000 2825,4150 3040,4150 3055,4135 3055,3778.93 3403.93,3430 3944,3430 4030,3516 4030,3752.43 4005,3777.43 4005,4315 v1(3985,4335)
  Layer 8 - Bottom Layer w5: U12.D3@1310.22,3930.89 v2(1323.01,3943.68) ; R205.1@3945,4285 R205.1@3945,4295
  Layer 8 - Bottom Layer w9.5: R205.1@3945,4295 v1(3985,4335)
DVP2_11: R206.2 U12.C2 | length 6136.5
  Layer 3 - Sensitive w5.5: v2(1348.6,3969.27) 1361.43,3982.1 1402.36,3982.1 ; 1402.36,3982.36 1487.87,4067.87 1487.87,4417.87 1535,4465 1743,4465 1755,4453 1755,4270 1765,4260 1809,4260 1817.5,4268.5 1817.5,4333.25 1824.25,4340 1855.75,4340 1862.5,4333.25 1862.5,4266.75 1869.25,4260 1900.75,4260 1907.5,4266.75 1907.5,4333.25 1914.25,4340 1945.75,4340 1952.5,4333.25 1952.5,4266.75 1959.25,4260 1990.75,4260 1997.5,4266.75 1997.5,4333.25 2004.25,4340 2035.75,4340 2042.5,4333.25 2042.5,4266.75 2049.25,4260 2080.75,4260 2087.5,4266.75 2087.5,4333.25 2094.25,4340 2125.75,4340 2132.5,4333.25 2132.5,4266.75 2139.25,4260 2170.75,4260 2177.5,4266.75 2177.5,4333.25 2184.25,4340 2215.75,4340 2222.5,4333.25 2222.5,4266.75 2229.25,4260 2260.75,4260 2267.5,4266.75 2267.5,4333.25 2274.25,4340 2305.75,4340 2312.5,4333.25 2312.5,4266.75 2319.25,4260 2350.75,4260 2357.5,4266.75 2357.5,4333.25 2364.25,4340 2395.75,4340 2402.5,4333.25 2402.5,4266.75 2409.25,4260 2440.75,4260 2447.5,4266.75 2447.5,4333.25 2454.25,4340 2485.75,4340 2492.5,4333.25 2492.5,4266.75 2499.25,4260 2530.75,4260 2537.5,4266.75 2537.5,4333.25 2544.25,4340 2575.75,4340 2582.5,4333.25 2582.5,4266.75 2589.25,4260 2620.75,4260 2627.5,4266.75 2627.5,4333.25 2634.25,4340 2665.75,4340 2672.5,4333.25 2672.5,4266.75 2679.25,4260 2710.75,4260 2717.5,4266.75 2717.5,4333.25 2724.25,4340 2755.75,4340 2762.5,4333.25 2762.5,4266.75 2769.25,4260 2800.75,4260 2807.5,4266.75 2807.5,4333.25 2814.25,4340 2845.75,4340 2852.5,4333.25 2852.5,4266.75 2859.25,4260 2890.75,4260 2897.5,4266.75 2897.5,4333.25 2904.25,4340 2935.75,4340 2942.5,4333.25 2942.5,4266.75 2949.25,4260 2980.75,4260 2987.5,4266.75 2987.5,4343.5 2995,4351 3094,4351 3100,4345 3100,3797.57 3422.57,3475 3890,3475 3975,3560 v1(3975,3725)
  Layer 8 - Bottom Layer w5: U12.C2@1335.81,3956.48 v2(1348.6,3969.27) ; R206.2@3944,3756 R206.2@3944,3762
  Layer 8 - Bottom Layer w9.5: R206.2@3944,3756 v1(3975,3725)
DVP2_HSYNC: R151.1 U12.A2 | length 6072.8
  Layer 3 - Sensitive w5.5: v2(1348.6,4020.45) 1348.6,4047.5 1440.63,4139.53 1440.63,4520.63 1570,4650 1600.75,4650 1607.5,4656.75 1607.5,4671.25 1614.25,4678 1645.75,4678 1652.5,4671.25 1652.5,4628.75 1659.25,4622 1690.75,4622 1697.5,4628.75 1697.5,4643.25 1704.25,4650 2955,4650 3145,4460 3145,3816.36 3441.36,3520 3832.43,3520 3905,3592.57 3905,3675 3925,3695 3925,3771.21 3875,3821.21 3875,4191.21 3755,4311.21 3755,4375 3820,4440 v1(4035,4440)
  Layer 8 - Bottom Layer w5: U12.A2@1335.81,4007.66 v2(1348.6,4020.45)
  Layer 8 - Bottom Layer w9.5: v1(4035,4440) 4053,4458 4692,4458 4760,4390 R151.1@4760,4283.62
DVP2_PCLK: R213.1 U12.B1 | length 6135.7
  Layer 3 - Sensitive w5.5: v2(1374.19,3994.86) 1394.86,3994.86 1472.13,4072.13 1472.13,4432.13 1520,4480 1766,4480 1775,4471 1775,4410 1785,4400 1820.75,4400 1827.5,4406.75 1827.5,4438.19 1834.25,4444.94 1865.75,4444.94 1872.5,4438.19 1872.5,4361.81 1879.25,4355.06 1910.75,4355.06 1917.5,4361.81 1917.5,4438.19 1924.25,4444.94 1955.75,4444.94 1962.5,4438.19 1962.5,4361.81 1969.25,4355.06 2000.75,4355.06 2007.5,4361.81 2007.5,4438.19 2014.25,4444.94 2045.75,4444.94 2052.5,4438.19 2052.5,4361.81 2059.25,4355.06 2090.75,4355.06 2097.5,4361.81 2097.5,4438.19 2104.25,4444.94 2135.75,4444.94 2142.5,4438.19 2142.5,4361.81 2149.25,4355.06 2180.75,4355.06 2187.5,4361.81 2187.5,4438.2 2194.25,4444.95 2225.75,4444.95 2232.5,4438.2 2232.5,4361.8 2239.25,4355.05 2270.75,4355.05 2277.5,4361.8 2277.5,4438.2 2284.25,4444.95 2315.75,4444.95 2322.5,4438.2 2322.5,4361.8 2329.25,4355.05 2360.75,4355.05 2367.5,4361.8 2367.5,4438.2 2374.25,4444.95 2405.75,4444.95 2412.5,4438.2 2412.5,4361.8 2419.25,4355.05 2450.75,4355.05 2457.5,4361.8 2457.5,4438.2 2464.25,4444.95 2495.75,4444.95 2502.5,4438.2 2502.5,4361.8 2509.25,4355.05 2540.75,4355.05 2547.5,4361.8 2547.5,4438.2 2554.25,4444.95 2585.75,4444.95 2592.5,4438.2 2592.5,4406.75 2599.25,4400 3074.85,4400 3115,4359.85 3115,3803.79 3428.79,3490 3865,3490 3955,3580 3955,3700 3940,3715 3940,3775 3910,3805 3910,4320 3885,4345 v1(3810,4345)
  Layer 8 - Bottom Layer w5: U12.B1@1361.4,3982.07 v2(1374.19,3994.86)
  Layer 8 - Bottom Layer w9.5: R213.1@3810,4283.62 v1(3810,4345)
DVP2_VSYNC: R221.1 U12.C1 | length 6136.3
  Layer 3 - Sensitive w5.5: v2(1374.19,3969.27) 1409.27,3969.27 1503.62,4063.62 1503.62,4396.62 1557,4450 1672,4450 1725,4397 1725,4233 1758,4200 1775.75,4200 1782.5,4206.75 1782.5,4233.25 1789.25,4240 1820.75,4240 1827.5,4233.25 1827.5,4166.75 1834.25,4160 1865.75,4160 1872.5,4166.75 1872.5,4233.25 1879.25,4240 1910.75,4240 1917.5,4233.25 1917.5,4166.75 1924.25,4160 1955.75,4160 1962.5,4166.75 1962.5,4233.25 1969.25,4240 2000.75,4240 2007.5,4233.25 2007.5,4166.75 2014.25,4160 2045.75,4160 2052.5,4166.75 2052.5,4233.25 2059.25,4240 2090.75,4240 2097.5,4233.25 2097.5,4166.75 2104.25,4160 2135.75,4160 2142.5,4166.75 2142.5,4233.25 2149.25,4240 2180.75,4240 2187.5,4233.25 2187.5,4166.75 2194.25,4160 2225.75,4160 2232.5,4166.75 2232.5,4233.25 2239.25,4240 2270.75,4240 2277.5,4233.25 2277.5,4166.75 2284.25,4160 2315.75,4160 2322.5,4166.75 2322.5,4233.25 2329.25,4240 2360.75,4240 2367.5,4233.25 2367.5,4166.75 2374.25,4160 2405.75,4160 2412.5,4166.75 2412.5,4233.25 2419.25,4240 2450.75,4240 2457.5,4233.25 2457.5,4206.75 2464.25,4200 3050,4200 3085,4165 3085,3791.36 3416.36,3460 3905,3460 4000,3555 4000,3740 3925,3815 3925,4330 3890,4365 v1(3780,4365)
  Layer 8 - Bottom Layer w5: U12.C1@1361.4,3956.48 v2(1374.19,3969.27)
  Layer 8 - Bottom Layer w9.5: R221.1@3495,4388.62 3541.38,4388.62 3565,4365 v1(3780,4365)
DVP3_04: R178.1
DVP3_05: R179.2
DVP3_06: R180.1
DVP3_07: R181.2
DVP3_08: R188.1
DVP3_09: R189.2
DVP3_10: R187.1
DVP3_11: R182.1
DVP3_HSYNC: R176.1
DVP3_PCLK: R224.2
DVP3_VSYNC: R177.2
DVP4_04: R215.1
DVP4_05: R216.2
DVP4_06: R217.1
DVP4_07: R218.2
DVP4_08: R219.1
DVP4_09: R220.2
DVP4_10: R223.1
DVP4_11: R222.2
DVP4_HSYNC: R200.2
DVP4_PCLK: R199.1
DVP4_VSYNC: R203.2
EVM_1V8: J10.3 J29.55 J29.56 | length 2360.3
  Layer 6 - Signal w40: v1(4128.93,3850) 4260,3850 4365,3955 4365,4070 4200,4235 v1(4128.93,4235) 4095,4268.93 4095,4554.27 4145.73,4605 4440,4605 4500,4665 J10.3@4500,5400
  Layer 8 - Bottom Layer w15: v1(4128.93,3850) J29.56@4128.93,3900.89 ; J29.55@4128.93,4143.8 v1(4128.93,4235)
EVM_3V3: J7.3 J29.57 J29.58 J29.59 J29.60 | length 3427.4
  Layer 6 - Signal w40: v1(4097.43,3951.77) v1(4065.93,3951.77) ; v1(4097.43,4092.91) v1(4065.93,4092.91) 4032.91,4092.91 3990,4050 3990,3995 4033.23,3951.77 v1(4065.93,3951.77) ; J7.3@4500,5900 4585,5815 4585,4595 4515,4525 4315,4525 4265,4475 4265,4270 4440,4095 4440,3925 4295,3780 4100,3780 4065.93,3814.07 v1(4065.93,3951.77)
  Layer 8 - Bottom Layer w15: J29.60@4065.93,3900.89 v1(4065.93,3951.77) ; v1(4065.93,4092.91) J29.59@4065.93,4143.8 ; J29.58@4097.43,3900.89 v1(4097.43,3951.77) ; v1(4097.43,4092.91) J29.57@4097.43,4143.8
EVM_5V5: J29.65 J29.66 | length 273.1
  Layer 6 - Signal w15: v1(3971.45,3951.77) 3935,3988.22 3935,4056.47 v1(3971.45,4092.91)
  Layer 8 - Bottom Layer w15: J29.66@3971.45,3900.89 v1(3971.45,3951.77) ; v1(3971.45,4092.91) J29.65@3971.45,4143.8
EVM_12V: J6.1 J8.1 J29.49 J29.50 J29.51 J29.52 J29.53 J29.54 | length 6173.4
  Layer 6 - Signal w40: J8.1@3350,5900 3350,5955 3300,6005 3300,6180 3350,6230 J6.1@3350,6305 3435,6390 3825,6390 4235,5980 4685,5980 4800,5865 4800,4615 4515,4330 4515,3895 4330,3710 4060,3710 3885,3885 3885,4088.85 3961.15,4165 4140,4165 4160.42,4144.58 v1(4160.42,4092.91) v1(4191.92,4092.91) v1(4223.41,4092.91) 4240,4076.33 4240,3968.36 v1(4223.41,3951.77) v1(4191.92,3951.77) v1(4160.42,3951.77)
  Layer 8 - Bottom Layer w15: J29.54@4160.42,3900.89 v1(4160.42,3951.77) ; v1(4160.42,4092.91) J29.53@4160.42,4143.8 ; J29.52@4191.92,3900.89 v1(4191.92,3951.77) ; v1(4191.92,4092.91) J29.51@4191.92,4143.8 ; J29.50@4223.41,3900.89 v1(4223.41,3951.77) ; v1(4223.41,4092.91) J29.49@4223.41,4143.8
FRAME_SYNC_OV1: J29.32 U8.F5 | length 6041.4
  Layer 6 - Signal w5: v2(1874.41,3049.41) 1887,3062 1908,3062 1913,3057 1913,3011 1903,3001 1903,2940
  Layer 6 - Signal w8: 1903,2940 1903,2852 1995,2760 1995,2630 2060,2565 2445,2565 2535,2655 2965,2655 3104,2794 5454,2794 v1(5465,2805)
  Layer 8 - Bottom Layer w5: v2(1874.41,3049.41) U8.F5@1887.2,3062.2
  Layer 8 - Bottom Layer w8: J29.32@4664.36,3900.89 4664.36,3944.36 4680,3960 5305,3960 5360,3905 5360,3370 5420,3310 5420,3140 5465,3095 v1(5465,2805)
FRAME_SYNC_OV2: J29.34 U12.F5 | length 6161.7
  Layer 6 - Signal w5: v2(1271.83,3866.91) 1259.24,3879.5 1259.24,3900.5 1264.24,3905.5 1310.24,3905.5 1320.24,3895.5 1381.24,3895.5
  Layer 6 - Signal w8: 1381.24,3895.5 1469.24,3895.5 1578.74,4005 2401.57,4005 2761.57,3645 3431.57,3645 3851.57,3225 5430,3225 v1(5445,3240)
  Layer 8 - Bottom Layer w5: U12.F5@1259.04,3879.7 v2(1271.83,3866.91)
  Layer 8 - Bottom Layer w8: J29.34@4632.86,3900.89 4632.86,3952.86 4660,3980 5313.28,3980 5380,3913.28 5380,3380 5445,3315 v1(5445,3240)
FSIN0_OV1: R64.1 R158.1 R163.1 U8.C9 | length 5763.6
  Layer 1 - Top Layer w5: v2(1976.77,3177.36) 2002.64,3177.36 2015.43,3164.57 2045,3164.57
  Layer 1 - Top Layer w8: 2045,3164.57 2261.81,3164.57 2261.81,3181.81 2270,3190 2390,3190 v1(2420,3160) ; R163.1@4406.38,1520 R158.1@4406.38,1565 v1(4406.38,1625)
  Layer 6 - Signal w8: v1(2420,3160) 2625,2955 v1(5365,2955)
  Layer 8 - Bottom Layer w5: U8.C9@1963.98,3164.57 v2(1976.77,3177.36)
  Layer 8 - Bottom Layer w8: v1(4406.38,1625) 4510,1728.62 4510,1945 4620,2055 5285,2055 5380,2150 5380,2940 v1(5365,2955)
FSIN0_OV2: R94.1 R161.1 R165.1 U12.C9 | length 7348.5
  Layer 1 - Top Layer w5: v2(1143.88,3969.27) 1143.88,3995.14 1156.67,4007.93 1156.67,4037.5
  Layer 1 - Top Layer w8: v1(1140,4410) 1131.24,4401.24 1131.24,4262.5 1139.43,4254.31 1156.67,4254.31 1156.67,4037.5 ; R161.1@5173.62,1435 R165.1@5173.62,1480 5205,1480 5215,1490 v1(5215,1635)
  Layer 6 - Signal w8: v1(1140,4410) 1185,4455 1630,4455 1959,4126 2453.55,4126 2814.55,3765 3481.27,3765 3901.27,3345 5220,3345 5260,3385 v1(5315,3385)
  Layer 8 - Bottom Layer w5: v2(1143.88,3969.27) U12.C9@1156.67,3956.48
  Layer 8 - Bottom Layer w8: v1(5215,1635) 5270,1690 5400,1690 5420,1710 5420,2995 5400,3015 5400,3300 v1(5315,3385)
FSIN1_OV1: R68.2 R157.1 R164.1 U8.A7 | length 6119
  Layer 1 - Top Layer w8: v1(4215,1655) 4215,1620 4240,1595 4240,1445 4300,1385 R164.1@4406.38,1385 R157.1@4406.38,1340
  Layer 6 - Signal w8: v1(2190,3075) 2375,3075 2560,2890 5340,2890 v1(5355,2875)
  Layer 8 - Bottom Layer w8: U8.A7@2015.16,3113.39 2026.61,3113.39 2035,3105 R68.2@2076.38,3105 2076.38,3078.62 2090,3065 2150,3065 2160,3075 v1(2190,3075) ; v1(4215,1655) 4260,1700 4455,1700 4487.5,1732.5 4487.5,1952.5 4610,2075 5275,2075 5360,2160 5360,2870 v1(5355,2875)
FSIN1_OV2: R98.2 R160.1 R166.1 U12.A7 | length 6931.8
  Layer 1 - Top Layer w8: R166.1@5173.62,1525 R160.1@5173.62,1570 5175,1571.38 v1(5175,1635)
  Layer 6 - Signal w8: v1(1310,4380) 1320,4390 1605,4390 1930,4065 2428.28,4065 2789.28,3704 3456.01,3704 3875.01,3285 5250,3285 5280,3315 v1(5350,3315)
  Layer 8 - Bottom Layer w8: U12.A7@1207.85,4007.66 1207.85,4019.11 1216.24,4027.5 R98.2@1216.24,4068.88 ; R98.2@1215,4071.38 1246.38,4071.38 1260,4085 1260,4275 1310,4325 v1(1310,4380) ; v1(5175,1635) 5250,1710 5390,1710 5400,1720 5400,2985 5380,3005 5380,3285 v1(5350,3315)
